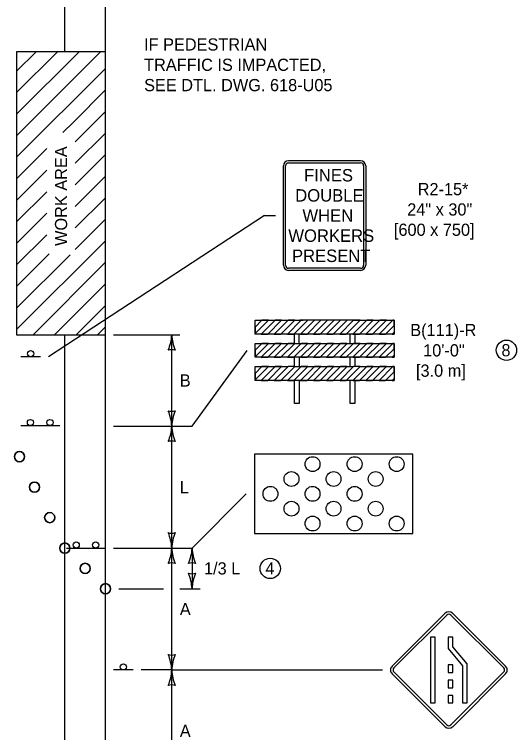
# Model space of a CAD drawing. Extents: x 49991.4 to 50021, y 49987.6 to 50011.4.
# Drawn here: x 50002.634 to 50005.106, y 50003.296 to 50006.831 of the extents above; entities that cross this region are included whole.
import ezdxf

# ---------------------------------------------------------------- set-up
doc = ezdxf.new("R2010")
doc.units = 0
for name, color, linetype in [('Level 1', 7, 'Continuous'), ('Level 2', 7, 'Continuous'), ('Level 3', 7, 'Continuous')]:
    doc.layers.add(name, color=color, linetype=linetype)

msp = doc.modelspace()

# ---------------------------------------------------------------- linework, layer by layer
at = {"layer": 'Level 1'}
for p, q in [((50002.8825, 50006.6477), (50002.8825, 50009.2134)), ((50003.0824, 50001.1514), (50003.0824, 50009.2134)), ((50003.0824, 50006.6477), (50002.6449, 50006.6477)), ((50002.6449, 50006.6477), (50002.6449, 50005.2541)), ((50002.6449, 50006.5521), (50002.7405, 50006.6477)), ((50002.6449, 50006.4461), (50002.8465, 50006.6477)), ((50002.6449, 50006.34), (50002.9526, 50006.6477)), ((50002.6449, 50006.234), (50003.0587, 50006.6477)), ((50002.6449, 50006.1279), (50003.0824, 50006.5654)), ((50002.9244, 50006.3013), (50003.0824, 50006.4593)), ((50002.9337, 50006.2045), (50003.0824, 50006.3532)), ((50002.8724, 50006.2493), (50002.9244, 50006.3013)), ((50002.9337, 50006.0984), (50003.0824, 50006.2472)), ((50002.6449, 50006.0218), (50002.7937, 50006.1706)), ((50002.9337, 50005.9924), (50003.0824, 50006.1411)), ((50003.9839, 50006.1112), (50004.3383, 50006.1112)), ((50003.9839, 50006.1006), (50004.3383, 50006.1006)), ((50004.1611, 50006.1112), (50004.1611, 50006.1112)), ((50002.6449, 50005.9158), (50002.7937, 50006.0645)), ((50003.9586, 50005.5964), (50003.9586, 50006.0858)), ((50003.9691, 50005.5964), (50003.9691, 50006.0858)), ((50004.3531, 50006.0858), (50004.3531, 50005.5964)), ((50004.3636, 50006.0858), (50004.3636, 50005.5964)), ((50002.9337, 50005.8863), (50003.0824, 50006.035)), ((50002.6449, 50005.8097), (50002.7937, 50005.9584)), ((50002.9337, 50005.7802), (50003.0824, 50005.929)), ((50002.6449, 50005.7036), (50002.7937, 50005.8524)), ((50002.9337, 50005.6742), (50003.0824, 50005.8229)), ((50002.6449, 50005.5976), (50002.7937, 50005.7463)), ((50002.6449, 50005.2794), (50003.0824, 50005.7169)), ((50002.6449, 50005.4915), (50002.8059, 50005.6525)), ((50002.6449, 50005.3854), (50002.9078, 50005.6483)), ((50002.7257, 50005.2541), (50003.0824, 50005.6108)), ((50004.3383, 50005.5816), (50003.9839, 50005.5816)), ((50004.3383, 50005.5711), (50003.9839, 50005.5711)), ((50002.8318, 50005.2541), (50003.0824, 50005.5047)), ((50002.9378, 50005.2541), (50003.0824, 50005.3987)), ((50003.8191, 50005.2598), (50003.885, 50005.3257)), ((50003.8191, 50005.2921), (50003.8527, 50005.3257)), ((50003.8527, 50005.3257), (50003.8191, 50005.2921)), ((50003.8191, 50005.2598), (50003.885, 50005.3257)), ((50003.8488, 50005.2573), (50003.9172, 50005.3257)), ((50003.9172, 50005.3257), (50003.8488, 50005.2573)), ((50003.881, 50005.2573), (50003.9494, 50005.3257)), ((50003.881, 50005.2573), (50003.9494, 50005.3257)), ((50003.9133, 50005.2573), (50003.9817, 50005.3257)), ((50003.9817, 50005.3257), (50003.9133, 50005.2573)), ((50003.9455, 50005.2573), (50004.0139, 50005.3257)), ((50003.9455, 50005.2573), (50004.0139, 50005.3257)), ((50003.9778, 50005.2573), (50004.0461, 50005.3257)), ((50004.01, 50005.2573), (50004.0784, 50005.3257)), ((50004.0243, 50005.3257), (50004.0556, 50005.3257)), ((50004.2836, 50005.3257), (50004.0386, 50005.3257)), ((50004.0424, 50005.2573), (50004.1108, 50005.3257)), ((50004.0746, 50005.2573), (50004.143, 50005.3257)), ((50004.1068, 50005.2573), (50004.1752, 50005.3257)), ((50004.139, 50005.2573), (50004.2074, 50005.3257)), ((50004.1712, 50005.2573), (50004.2396, 50005.3257)), ((50004.2035, 50005.2573), (50004.2718, 50005.3257)), ((50004.2357, 50005.2573), (50004.304, 50005.3257)), ((50004.304, 50005.3257), (50004.2642, 50005.3257)), ((50004.2679, 50005.2573), (50004.3363, 50005.3257)), ((50004.3001, 50005.2573), (50004.3685, 50005.3257)), ((50004.3685, 50005.3257), (50004.3001, 50005.2573)), ((50004.3324, 50005.2573), (50004.4008, 50005.3257)), ((50004.3324, 50005.2573), (50004.4008, 50005.3257)), ((50004.3646, 50005.2573), (50004.433, 50005.3257)), ((50004.433, 50005.3257), (50004.3646, 50005.2573)), ((50004.3968, 50005.2573), (50004.4652, 50005.3257)), ((50004.3968, 50005.2573), (50004.4652, 50005.3257)), ((50004.4291, 50005.2573), (50004.4975, 50005.3257)), ((50004.4975, 50005.3257), (50004.4291, 50005.2573)), ((50003.0439, 50005.2541), (50003.0824, 50005.2926)), ((50004.4613, 50005.2573), (50004.5031, 50005.299)), ((50004.4613, 50005.2573), (50004.5031, 50005.299)), ((50002.6449, 50005.2541), (50003.0824, 50005.2541)), ((50002.8825, 50001.1514), (50002.8825, 50005.2541)), ((50004.0357, 50005.2117), (50004.0357, 50005.2573)), ((50004.2865, 50005.2117), (50004.2865, 50005.2573)), ((50004.4936, 50005.2573), (50004.5031, 50005.2668)), ((50004.5031, 50005.2668), (50004.4936, 50005.2573)), ((50003.8191, 50005.1459), (50003.885, 50005.2117)), ((50003.8191, 50005.1781), (50003.8527, 50005.2117)), ((50003.8527, 50005.2117), (50003.8191, 50005.1781)), ((50003.8191, 50005.1459), (50003.885, 50005.2117)), ((50003.8488, 50005.1433), (50003.9172, 50005.2117)), ((50003.9172, 50005.2117), (50003.8488, 50005.1433)), ((50003.881, 50005.1433), (50003.9494, 50005.2117)), ((50003.881, 50005.1433), (50003.9494, 50005.2117)), ((50003.9133, 50005.1433), (50003.9817, 50005.2117)), ((50003.9817, 50005.2117), (50003.9133, 50005.1433)), ((50003.9455, 50005.1433), (50004.0139, 50005.2117)), ((50003.9455, 50005.1433), (50004.0139, 50005.2117)), ((50003.9778, 50005.1433), (50004.0461, 50005.2117)), ((50004.01, 50005.1433), (50004.0784, 50005.2117)), ((50004.0422, 50005.1433), (50004.1106, 50005.2117)), ((50004.0745, 50005.1433), (50004.1429, 50005.2117)), ((50004.1067, 50005.1433), (50004.1751, 50005.2117)), ((50004.1389, 50005.1433), (50004.2073, 50005.2117)), ((50004.1712, 50005.1433), (50004.2396, 50005.2117)), ((50004.2034, 50005.1433), (50004.2718, 50005.2117)), ((50004.2979, 50005.1734), (50004.3363, 50005.2117)), ((50004.2979, 50005.2056), (50004.304, 50005.2117)), ((50004.3001, 50005.1433), (50004.3685, 50005.2117)), ((50004.3685, 50005.2117), (50004.3001, 50005.1433)), ((50004.3324, 50005.1433), (50004.4008, 50005.2117)), ((50004.3324, 50005.1433), (50004.4008, 50005.2117)), ((50004.3646, 50005.1433), (50004.433, 50005.2117)), ((50004.433, 50005.2117), (50004.3646, 50005.1433)), ((50004.3968, 50005.1433), (50004.4652, 50005.2117)), ((50004.3968, 50005.1433), (50004.4652, 50005.2117)), ((50004.4291, 50005.1433), (50004.4975, 50005.2117)), ((50004.4975, 50005.2117), (50004.4291, 50005.1433)), ((50004.2357, 50005.1433), (50004.2979, 50005.2056)), ((50004.4613, 50005.1433), (50004.5031, 50005.1851)), ((50004.4613, 50005.1433), (50004.5031, 50005.1851)), ((50002.7625, 50005.1459), (50002.6665, 50005.1459)), ((50004.2679, 50005.1433), (50004.2979, 50005.1734)), ((50004.4936, 50005.1433), (50004.5031, 50005.1529)), ((50004.5031, 50005.1529), (50004.4936, 50005.1433)), ((50003.8191, 50005.0319), (50003.885, 50005.0978)), ((50003.8191, 50005.0642), (50003.8527, 50005.0978)), ((50003.8527, 50005.0978), (50003.8191, 50005.0642)), ((50003.8191, 50005.0319), (50003.885, 50005.0978)), ((50003.8488, 50005.0294), (50003.9172, 50005.0978)), ((50003.9172, 50005.0978), (50003.8488, 50005.0294)), ((50003.881, 50005.0294), (50003.9494, 50005.0978)), ((50003.881, 50005.0294), (50003.9494, 50005.0978)), ((50003.9133, 50005.0294), (50003.9817, 50005.0978)), ((50003.9817, 50005.0978), (50003.9133, 50005.0294)), ((50003.9455, 50005.0294), (50004.0139, 50005.0978)), ((50003.9455, 50005.0294), (50004.0139, 50005.0978)), ((50003.9778, 50005.0294), (50004.0461, 50005.0978)), ((50004.0461, 50005.0978), (50003.9778, 50005.0294)), ((50004.01, 50005.0294), (50004.0784, 50005.0978)), ((50004.01, 50005.0294), (50004.0784, 50005.0978)), ((50004.0422, 50005.0294), (50004.1106, 50005.0978)), ((50004.1106, 50005.0978), (50004.0422, 50005.0294)), ((50004.0745, 50005.0294), (50004.1429, 50005.0978)), ((50004.0745, 50005.0294), (50004.1429, 50005.0978)), ((50004.1067, 50005.0294), (50004.1751, 50005.0978)), ((50004.1751, 50005.0978), (50004.1067, 50005.0294)), ((50004.1389, 50005.0294), (50004.2073, 50005.0978)), ((50004.1389, 50005.0294), (50004.2073, 50005.0978)), ((50004.1712, 50005.0294), (50004.2396, 50005.0978)), ((50004.2396, 50005.0978), (50004.1712, 50005.0294)), ((50004.2034, 50005.0294), (50004.2718, 50005.0978)), ((50004.2034, 50005.0294), (50004.2718, 50005.0978)), ((50004.2357, 50005.0294), (50004.304, 50005.0978)), ((50004.304, 50005.0978), (50004.2357, 50005.0294)), ((50004.2679, 50005.0294), (50004.3363, 50005.0978)), ((50004.2679, 50005.0294), (50004.3363, 50005.0978)), ((50004.3001, 50005.0294), (50004.3685, 50005.0978)), ((50004.3685, 50005.0978), (50004.3001, 50005.0294)), ((50004.3324, 50005.0294), (50004.4008, 50005.0978)), ((50004.3324, 50005.0294), (50004.4008, 50005.0978)), ((50004.3646, 50005.0294), (50004.433, 50005.0978)), ((50004.433, 50005.0978), (50004.3646, 50005.0294)), ((50004.3968, 50005.0294), (50004.4652, 50005.0978)), ((50004.3968, 50005.0294), (50004.4652, 50005.0978)), ((50004.4291, 50005.0294), (50004.4975, 50005.0978)), ((50004.4975, 50005.0978), (50004.4291, 50005.0294)), ((50004.4613, 50005.0294), (50004.5031, 50005.0711)), ((50004.4613, 50005.0294), (50004.5031, 50005.0711)), ((50004.4936, 50005.0294), (50004.5031, 50005.0389)), ((50004.5031, 50005.0389), (50004.4936, 50005.0294)), ((50002.6651, 50004.807), (50002.7611, 50004.807)), ((50002.7611, 50004.807), (50002.8571, 50004.807)), ((50002.8904, 50004.2041), (50002.9864, 50004.2041)), ((50002.9864, 50004.2041), (50003.0824, 50004.2041)), ((50004.7541, 50003.8834), (50004.4937, 50003.6226)), ((50004.7629, 50003.8746), (50004.5025, 50003.6139)), ((50005.0433, 50003.6139), (50004.7828, 50003.8745)), ((50005.0521, 50003.6227), (50004.7915, 50003.8833)), ((50004.7057, 50003.7663), (50004.6823, 50003.7663)), ((50004.6823, 50003.7663), (50004.6825, 50003.442)), ((50004.7059, 50003.4421), (50004.7057, 50003.7663)), ((50004.7923, 50003.7663), (50004.7689, 50003.7663)), ((50004.7689, 50003.7663), (50004.7689, 50003.7092)), ((50004.7924, 50003.7178), (50004.7923, 50003.7663)), ((50004.7689, 50003.7092), (50004.8399, 50003.6248)), ((50004.8635, 50003.634), (50004.7924, 50003.7178)), ((50004.7924, 50003.6297), (50004.769, 50003.6297)), ((50004.769, 50003.6297), (50004.769, 50003.5921)), ((50004.7925, 50003.5921), (50004.7924, 50003.6297)), ((50004.8399, 50003.6248), (50004.84, 50003.4416)), ((50004.8635, 50003.4416), (50004.8635, 50003.634)), ((50003.2184, 50003.6041), (50003.1224, 50003.6041)), ((50004.4936, 50003.5855), (50004.7542, 50003.3246)), ((50004.5024, 50003.5943), (50004.763, 50003.3333)), ((50004.769, 50003.5921), (50004.7925, 50003.5921)), ((50004.7828, 50003.3334), (50005.0434, 50003.5942)), ((50004.7916, 50003.3246), (50005.0522, 50003.5855)), ((50004.7925, 50003.5545), (50004.769, 50003.5544)), ((50004.769, 50003.5544), (50004.7691, 50003.5168)), ((50004.7925, 50003.5168), (50004.7925, 50003.5545)), ((50004.7691, 50003.5168), (50004.7925, 50003.5168)), ((50004.7925, 50003.4792), (50004.7691, 50003.4792)), ((50004.7691, 50003.4792), (50004.7691, 50003.4415)), ((50004.7926, 50003.4416), (50004.7925, 50003.4792)), ((50004.6825, 50003.442), (50004.7059, 50003.4421)), ((50004.7691, 50003.4415), (50004.7926, 50003.4416)), ((50004.84, 50003.4416), (50004.8635, 50003.4416))]:
    msp.add_line(p, q, dxfattribs=at)
for points in [[(50004.2979, 50005.2573), (50003.8191, 50005.2573), (50003.8191, 50005.3257), (50004.0243, 50005.3257)], [(50003.885, 50005.3257), (50003.8527, 50005.3257)], [(50003.9494, 50005.3257), (50003.9172, 50005.3257)], [(50004.0784, 50005.3257), (50004.0556, 50005.3257), (50004.0461, 50005.3257), (50003.9778, 50005.2573), (50004.01, 50005.2573), (50004.0784, 50005.3257)], [(50004.0139, 50005.3257), (50003.9817, 50005.3257)], [(50004.143, 50005.3257), (50004.1108, 50005.3257), (50004.0424, 50005.2573), (50004.0746, 50005.2573), (50004.143, 50005.3257)], [(50004.2074, 50005.3257), (50004.1752, 50005.3257), (50004.1068, 50005.2573), (50004.139, 50005.2573), (50004.2074, 50005.3257)], [(50004.2718, 50005.3257), (50004.2642, 50005.3257), (50004.2396, 50005.3257), (50004.1712, 50005.2573), (50004.2035, 50005.2573), (50004.2718, 50005.3257)], [(50004.2357, 50005.2573), (50004.2679, 50005.2573), (50004.3363, 50005.3257), (50004.304, 50005.3257), (50004.2357, 50005.2573)], [(50004.2979, 50005.3257), (50004.5031, 50005.3257), (50004.5031, 50005.2573), (50004.2979, 50005.2573)], [(50004.4008, 50005.3257), (50004.3685, 50005.3257)], [(50004.4652, 50005.3257), (50004.433, 50005.3257)], [(50004.5031, 50005.299), (50004.5031, 50005.3257), (50004.4975, 50005.3257)], [(50003.8191, 50005.2921), (50003.8191, 50005.2598)], [(50003.8488, 50005.2573), (50003.881, 50005.2573)], [(50003.9133, 50005.2573), (50003.9455, 50005.2573)], [(50004.0129, 50005.2117), (50004.0129, 50005.2573)], [(50004.3001, 50005.2573), (50004.3324, 50005.2573)], [(50004.3093, 50005.2573), (50004.3093, 50005.2117)], [(50004.3646, 50005.2573), (50004.3968, 50005.2573)], [(50004.4291, 50005.2573), (50004.4613, 50005.2573)], [(50004.4936, 50005.2573), (50004.5031, 50005.2573), (50004.5031, 50005.2668)], [(50004.2979, 50005.2117), (50004.5031, 50005.2117), (50004.5031, 50005.1433), (50003.8191, 50005.1433), (50003.8191, 50005.2117), (50004.2979, 50005.2117)], [(50003.885, 50005.2117), (50003.8527, 50005.2117)], [(50003.9494, 50005.2117), (50003.9172, 50005.2117)], [(50004.0784, 50005.2117), (50004.0461, 50005.2117), (50003.9778, 50005.1433), (50004.01, 50005.1433), (50004.0784, 50005.2117)], [(50004.0139, 50005.2117), (50003.9817, 50005.2117)], [(50004.1429, 50005.2117), (50004.1106, 50005.2117), (50004.0422, 50005.1433), (50004.0745, 50005.1433), (50004.1429, 50005.2117)], [(50004.2073, 50005.2117), (50004.1751, 50005.2117), (50004.1067, 50005.1433), (50004.1389, 50005.1433), (50004.2073, 50005.2117)], [(50004.2718, 50005.2117), (50004.2396, 50005.2117), (50004.1712, 50005.1433), (50004.2034, 50005.1433), (50004.2718, 50005.2117)], [(50004.2357, 50005.1433), (50004.2679, 50005.1433), (50004.2979, 50005.1734), (50004.3363, 50005.2117), (50004.3093, 50005.2117), (50004.304, 50005.2117), (50004.2979, 50005.2056), (50004.2357, 50005.1433)], [(50004.4008, 50005.2117), (50004.3685, 50005.2117)], [(50004.4652, 50005.2117), (50004.433, 50005.2117)], [(50004.5031, 50005.1851), (50004.5031, 50005.2117), (50004.4975, 50005.2117)], [(50003.8191, 50005.1781), (50003.8191, 50005.1459)], [(50003.8488, 50005.1433), (50003.881, 50005.1433)], [(50003.9133, 50005.1433), (50003.9455, 50005.1433)], [(50004.0129, 50005.0978), (50004.0129, 50005.1433)], [(50004.0357, 50005.1433), (50004.0357, 50005.0978)], [(50004.2865, 50005.0978), (50004.2865, 50005.1433)], [(50004.3001, 50005.1433), (50004.3324, 50005.1433)], [(50004.3093, 50005.1433), (50004.3093, 50005.0978)], [(50004.3646, 50005.1433), (50004.3968, 50005.1433)], [(50004.4291, 50005.1433), (50004.4613, 50005.1433)], [(50004.4936, 50005.1433), (50004.5031, 50005.1433), (50004.5031, 50005.1529)], [(50004.3363, 50005.0978), (50004.5031, 50005.0978), (50004.5031, 50005.0294), (50003.8191, 50005.0294), (50003.8191, 50005.0978), (50003.9817, 50005.0978)], [(50003.885, 50005.0978), (50003.8527, 50005.0978)], [(50003.9494, 50005.0978), (50003.9172, 50005.0978)], [(50004.0139, 50005.0978), (50003.9817, 50005.0978)], [(50004.0139, 50005.0978), (50004.304, 50005.0978)], [(50004.0784, 50005.0978), (50004.0461, 50005.0978)], [(50004.1429, 50005.0978), (50004.1106, 50005.0978)], [(50004.2073, 50005.0978), (50004.1751, 50005.0978)], [(50004.2718, 50005.0978), (50004.2396, 50005.0978)], [(50004.3363, 50005.0978), (50004.304, 50005.0978)], [(50004.4008, 50005.0978), (50004.3685, 50005.0978)], [(50004.4652, 50005.0978), (50004.433, 50005.0978)], [(50004.5031, 50005.0711), (50004.5031, 50005.0978), (50004.4975, 50005.0978)], [(50003.8191, 50005.0642), (50003.8191, 50005.0319)], [(50004.4936, 50005.0294), (50004.5031, 50005.0294), (50004.5031, 50005.0389)], [(50003.8488, 50005.0294), (50003.881, 50005.0294)], [(50003.9133, 50005.0294), (50003.9455, 50005.0294)], [(50003.9778, 50005.0294), (50004.01, 50005.0294)], [(50004.0357, 50005.0293), (50004.0357, 50004.9153), (50004.0129, 50004.9153), (50004.0129, 50005.0293)], [(50004.0422, 50005.0294), (50004.0745, 50005.0294)], [(50004.1067, 50005.0294), (50004.1389, 50005.0294)], [(50004.1712, 50005.0294), (50004.2034, 50005.0294)], [(50004.2357, 50005.0294), (50004.2679, 50005.0294)], [(50004.3093, 50005.0293), (50004.3093, 50004.9153), (50004.2865, 50004.9153), (50004.2865, 50005.0293)], [(50004.3001, 50005.0294), (50004.3324, 50005.0294)], [(50004.3646, 50005.0294), (50004.3968, 50005.0294)], [(50004.4291, 50005.0294), (50004.4613, 50005.0294)]]:
    msp.add_lwpolyline(points, dxfattribs=at)
msp.add_lwpolyline([(50003.8155, 50004.2763), (50004.5952, 50004.2763), (50004.5952, 50004.6663), (50003.8155, 50004.6663)], close=True, dxfattribs=at)
msp.add_lwpolyline([(50003.8155, 50004.2763), (50004.5952, 50004.2763), (50004.5952, 50004.6663), (50003.8155, 50004.6663)], close=True, dxfattribs=at)
for centre, radius in [((50002.7145, 50005.161), 0.0152), ((50002.7131, 50004.8222), 0.0152), ((50002.8091, 50004.8222), 0.0152), ((50002.6588, 50004.6541), 0.025), ((50004.1017, 50004.6173), 0.0366), ((50004.1017, 50004.6173), 0.0366), ((50004.3088, 50004.6173), 0.0366), ((50004.3088, 50004.6173), 0.0366), ((50004.5159, 50004.6173), 0.0366), ((50004.5159, 50004.6173), 0.0366), ((50003.9981, 50004.5442), 0.0366), ((50003.9981, 50004.5442), 0.0366), ((50004.2052, 50004.5442), 0.0366), ((50004.2052, 50004.5442), 0.0366), ((50004.4123, 50004.5442), 0.0366), ((50004.4123, 50004.5442), 0.0366), ((50002.7334, 50004.5041), 0.025), ((50003.8945, 50004.4711), 0.0366), ((50003.8945, 50004.4711), 0.0366), ((50004.1017, 50004.4711), 0.0366), ((50004.1017, 50004.4711), 0.0366), ((50004.3088, 50004.4711), 0.0366), ((50004.3088, 50004.4711), 0.0366), ((50003.9981, 50004.398), 0.0366), ((50003.9981, 50004.398), 0.0366), ((50004.2052, 50004.398), 0.0366), ((50004.2052, 50004.398), 0.0366), ((50004.4123, 50004.398), 0.0366), ((50004.4123, 50004.398), 0.0366), ((50002.808, 50004.3541), 0.025), ((50004.1017, 50004.3248), 0.0366), ((50004.1017, 50004.3248), 0.0366), ((50004.3088, 50004.3248), 0.0366), ((50004.3088, 50004.3248), 0.0366), ((50004.5159, 50004.3248), 0.0366), ((50004.5159, 50004.3248), 0.0366), ((50002.8825, 50004.2041), 0.025), ((50002.9384, 50004.2193), 0.0152), ((50003.0344, 50004.2193), 0.0152), ((50002.9825, 50004.1041), 0.025), ((50003.0824, 50004.0041), 0.025), ((50003.1704, 50003.6192), 0.0152)]:
    msp.add_circle(centre, radius, dxfattribs=at)
for centre, radius, start, end in [((50003.9839, 50006.0858), 0.0253, 90, 180), ((50003.9839, 50006.0858), 0.0148, 90, 180), ((50004.3383, 50006.0858), 0.0253, 0, 90), ((50004.3383, 50006.0858), 0.0148, 0, 90), ((50003.9839, 50005.5964), 0.0253, 180, 270), ((50003.9839, 50005.5964), 0.0148, 180, 270), ((50004.3383, 50005.5964), 0.0148, 270, 360), ((50004.3383, 50005.5964), 0.0253, 270, 360), ((50002.6588, 50004.6541), 0.025, 0, 180), ((50002.6588, 50004.6541), 0.025, 180, 0), ((50002.7334, 50004.5041), 0.025, 0, 180), ((50002.7334, 50004.5041), 0.025, 180, 0), ((50002.808, 50004.3541), 0.025, 0, 180), ((50002.808, 50004.3541), 0.025, 180, 0), ((50002.8825, 50004.2041), 0.025, 0, 180), ((50002.8825, 50004.2041), 0.025, 180, 0), ((50002.9825, 50004.1041), 0.025, 0, 180), ((50002.9825, 50004.1041), 0.025, 180, 0), ((50003.0824, 50004.0041), 0.025, 0, 180), ((50003.0824, 50004.0041), 0.025, 180, 0), ((50004.7729, 50003.8647), 0.0263, 45.0001, 134.9999), ((50004.7728, 50003.8648), 0.0139, 45.0001, 134.9999), ((50004.5121, 50003.6041), 0.0263, 134.9999, 225.0001), ((50005.0335, 50003.6041), 0.0263, 314.9999, 45.0001), ((50004.5121, 50003.6041), 0.0139, 134.9999, 225.0001), ((50005.0335, 50003.6041), 0.0139, 314.9999, 45.0001), ((50004.7728, 50003.3434), 0.0263, 225.0001, 314.9999), ((50004.7728, 50003.3434), 0.0139, 225.0001, 314.9999)]:
    msp.add_arc(centre, radius, start, end, dxfattribs=at)
at = {"layer": 'Level 2'}
for centre in [(50005.0564, 50005.178), (50003.8934, 50004.1041)]:
    msp.add_circle(centre, 0.0501, dxfattribs=at)
at = {"layer": 'Level 3'}
for p, q in [((50003.8647, 50005.8411), (50002.8025, 50005.1459)), ((50003.8647, 50005.8411), (50003.9186, 50005.8411)), ((50003.1224, 50005.2541), (50003.4484, 50005.2541)), ((50003.4084, 50004.8041), (50003.4084, 50005.2541)), ((50003.5084, 50004.8041), (50003.7791, 50005.1775)), ((50003.1224, 50004.8041), (50003.5084, 50004.8041)), ((50003.4084, 50004.2041), (50003.4084, 50004.8041)), ((50003.5084, 50004.2041), (50003.7755, 50004.4713)), ((50003.1224, 50004.2041), (50003.5084, 50004.2041)), ((50003.4084, 50003.6041), (50003.4084, 50004.2041)), ((50003.5084, 50004.2041), (50003.5084, 50004.0041)), ((50003.1474, 50004.0041), (50003.3684, 50004.0041)), ((50003.4484, 50004.0041), (50003.5484, 50004.0041)), ((50003.4084, 50003.6041), (50003.2584, 50003.6041)), ((50003.4084, 50003.6041), (50003.5084, 50003.6041)), ((50003.4084, 50003.0041), (50003.4084, 50003.6041)), ((50003.5084, 50003.6041), (50004.4458, 50003.6041))]:
    msp.add_line(p, q, dxfattribs=at)
for centre, radius, start, end in [((50003.1863, 50005.2632), 0.2223, 337.456, 357.6395), ((50003.6411, 50005.2656), 0.233, 182.8273, 202.0772), ((50003.4084, 50005.1259), 0.0548, 72.1388, 107.8612), ((50003.4084, 50004.9323), 0.0548, 252.1388, 287.8612), ((50003.1757, 50004.7926), 0.233, 2.8273, 22.0772), ((50003.6305, 50004.7949), 0.2223, 157.456, 177.6395), ((50003.1863, 50004.8132), 0.2223, 337.456, 357.6395), ((50003.6411, 50004.8156), 0.233, 182.8273, 202.0772), ((50003.4084, 50004.6759), 0.0548, 72.1388, 107.8612), ((50003.4084, 50004.3323), 0.0548, 252.1388, 287.8612), ((50003.1757, 50004.1926), 0.233, 2.8273, 22.0772), ((50003.6305, 50004.1949), 0.2223, 157.456, 177.6395), ((50003.1863, 50004.2132), 0.2223, 337.456, 357.6395), ((50003.6411, 50004.2156), 0.233, 182.8273, 202.0772), ((50003.2863, 50004.2132), 0.2223, 337.456, 357.6395), ((50003.7411, 50004.2156), 0.233, 182.8273, 202.0772), ((50003.4084, 50004.0759), 0.0548, 72.1388, 107.8612), ((50003.5084, 50004.0759), 0.0548, 72.1388, 107.8612), ((50003.5084, 50004.1323), 0.0548, 252.1388, 287.8612), ((50003.2757, 50003.9926), 0.233, 2.8273, 22.0772), ((50003.7305, 50003.9949), 0.2223, 157.456, 177.6395), ((50003.4084, 50003.7323), 0.0548, 252.1388, 287.8612), ((50003.1757, 50003.5926), 0.233, 2.8273, 22.0772), ((50003.6305, 50003.5949), 0.2223, 157.456, 177.6395), ((50003.1863, 50003.6132), 0.2223, 337.456, 357.6395), ((50003.6411, 50003.6156), 0.233, 182.8273, 202.0772), ((50003.4084, 50003.4759), 0.0548, 72.1388, 107.8612)]:
    msp.add_arc(centre, radius, start, end, dxfattribs=at)

# ---------------------------------------------------------------- texts
at = {"layer": 'Level 1'}
for s, height, p in [('IF PEDESTRIAN ', 0.06, (50003.2725, 50006.6532)), ('TRAFFIC IS IMPACTED, ', 0.06, (50003.2725, 50006.5532)), ('SEE DTL. DWG. 618-U05', 0.06, (50003.2725, 50006.4532)), ('FINES', 0.06118, (50004.06, 50006.0088)), ('DOUBLE', 0.06118, (50004.0165, 50005.9097)), ('WHEN', 0.06118, (50004.052, 50005.8105)), ('WORKERS', 0.06118, (50003.9825, 50005.7114)), ('PRESENT', 0.06118, (50004.0006, 50005.6122))]:
    msp.add_text(s, height=height, dxfattribs=at).set_placement(p)
at = {"layer": 'Level 2'}
for s, rotation, p in [('WORK AREA', 90, (50002.8937, 50005.6913)), ('A', 360, (50003.4484, 50003.8741)), ('A', 360, (50003.4484, 50003.2741))]:
    msp.add_text(s, height=0.06, rotation=rotation, dxfattribs=at).set_placement(p)
for s, p in [('R2-15*', (50004.6194, 50005.9411)), ('24" x 30"', (50004.5679, 50005.8411)), ('[600 x 750]', (50004.5023, 50005.7411)), ('B(111)-R', (50004.5828, 50005.2475)), ('10\'-0"', (50004.6463, 50005.1475)), ('8', (50005.0316, 50005.1481)), ('[3.0 m]', (50004.611, 50005.0475)), ('B', (50003.4484, 50004.9991)), ('L', (50003.4484, 50004.4741)), ('1/3 L', (50003.5675, 50004.0741)), ('4', (50003.8695, 50004.0741))]:
    msp.add_text(s, height=0.06, dxfattribs=at).set_placement(p)

doc.saveas('drawing.dxf')
